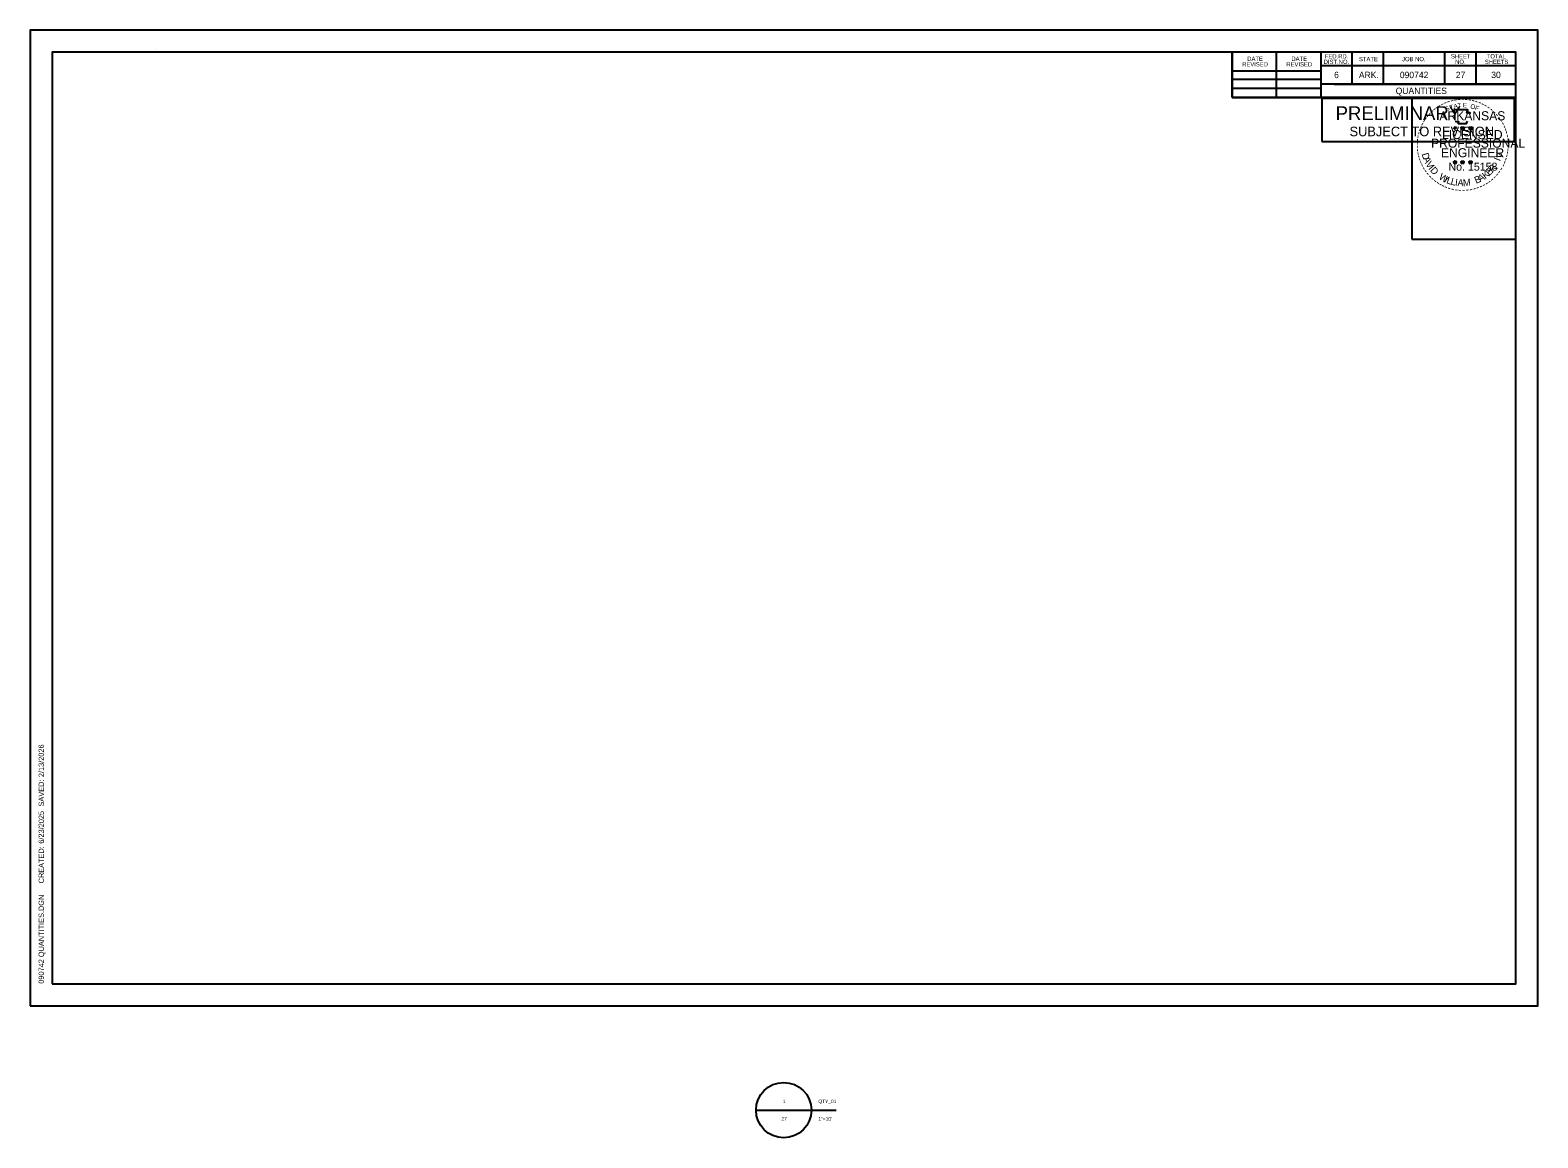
# Model space of a CAD drawing. Extents: x 0 to 373, y -15 to 110.
import ezdxf

# ---------------------------------------------------------------- set-up
doc = ezdxf.new("R2010")
doc.units = 0
for name, color, linetype in [('Default', 7, 'Continuous'), ('SHET_Annotations', 7, 'Continuous'), ('SHET_Border-Lines', 7, 'Continuous'), ('SHET_Border-Text', 7, 'Continuous'), ('SHET_Stamp-Prelim', 7, 'Continuous'), ('SHET_Stamp-Seal', 7, 'Continuous')]:
    doc.layers.add(name, color=color, linetype=linetype)

msp = doc.modelspace()

# ---------------------------------------------------------------- linework, layer by layer
at = {"layer": 'Default'}
for p, q in [((81.85, -11.75), (88.1, -11.75)), ((85, -11.75), (90.87, -11.75))]:
    msp.add_line(p, q, dxfattribs=at)
msp.add_circle((84.97, -11.75), 3.12, dxfattribs=at)
at = {"layer": 'SHET_Border-Lines'}
for p, q in [((14.11, 107.86), (14.11, 107.86)), ((14.11, 107.86), (14.11, 107.86)), ((135.55, 102.41), (135.55, 107.5)), ((140.54, 102.41), (140.54, 107.5)), ((145.52, 107.5), (145.52, 102.41)), ((149.01, 107.5), (149.01, 103.92)), ((152.55, 107.5), (152.55, 103.92)), ((159.47, 107.5), (159.47, 103.92)), ((163.01, 107.5), (163.01, 103.92)), ((135.55, 105.43), (145.52, 105.43)), ((167.5, 105.98), (145.52, 105.98)), ((167.5, 105.99), (167.5, 105.99)), ((135.55, 104.47), (145.52, 104.47)), ((167.5, 103.92), (145.52, 103.92)), ((147.03, 103.92), (167.5, 103.92)), ((135.55, 103.47), (145.52, 103.47)), ((167.5, 102.41), (135.55, 102.41))]:
    msp.add_line(p, q, dxfattribs=at)
for points in [[(0, 0), (170, 0), (170, 110), (0, 110)], [(2.5, 2.5), (167.5, 2.5), (167.5, 107.5), (2.5, 107.5)], [(135.55, 102.41), (167.5, 102.41), (167.5, 107.5), (135.55, 107.5)]]:
    msp.add_lwpolyline(points, close=True, dxfattribs=at)
at = {"layer": 'SHET_Stamp-Prelim'}
for points in [[(145.64, 97.43), (167.38, 97.43), (167.38, 102.29), (145.64, 102.29)], [(156.42, 102.36), (156.6, 102.36), (156.6, 102.4), (156.42, 102.4)]]:
    msp.add_lwpolyline(points, close=True, dxfattribs=at)
at = {"layer": 'SHET_Stamp-Seal'}
for p, q in [((160.48, 99.03), (160.66, 98.97)), ((160.48, 99.03), (160.61, 99)), ((160.48, 99.03), (160.6, 98.96)), ((160.55, 98.82), (160.66, 98.97)), ((160.55, 98.82), (160.61, 98.94)), ((160.55, 98.82), (160.66, 98.93)), ((160.66, 99.15), (160.64, 99.03)), ((160.66, 98.97), (160.66, 99.15)), ((160.66, 99.15), (160.68, 99.03)), ((160.83, 99.03), (160.66, 98.97)), ((160.77, 98.82), (160.66, 98.97)), ((160.77, 98.82), (160.66, 98.93)), ((160.83, 99.03), (160.69, 99)), ((160.77, 98.82), (160.7, 98.97)), ((160.83, 99.03), (160.73, 98.97)), ((161.33, 99.03), (161.51, 98.97)), ((161.33, 99.03), (161.46, 99)), ((161.33, 99.03), (161.45, 98.96)), ((161.4, 98.82), (161.51, 98.97)), ((161.4, 98.82), (161.46, 98.94)), ((161.4, 98.82), (161.51, 98.93)), ((161.51, 99.15), (161.49, 99.03)), ((161.51, 98.97), (161.51, 99.15)), ((161.51, 99.15), (161.53, 99.03)), ((161.69, 99.03), (161.51, 98.97)), ((161.62, 98.82), (161.51, 98.97)), ((161.62, 98.82), (161.51, 98.93)), ((161.69, 99.03), (161.54, 99)), ((161.62, 98.82), (161.55, 98.97)), ((161.69, 99.03), (161.58, 98.97)), ((162.23, 99.02), (162.41, 98.96)), ((162.23, 99.02), (162.36, 99)), ((162.23, 99.02), (162.35, 98.96)), ((162.3, 98.81), (162.41, 98.96)), ((162.3, 98.81), (162.36, 98.94)), ((162.3, 98.81), (162.41, 98.92)), ((162.41, 99.15), (162.39, 99.02)), ((162.41, 98.96), (162.41, 99.15)), ((162.41, 99.15), (162.43, 99.02)), ((162.59, 99.02), (162.41, 98.96)), ((162.52, 98.81), (162.41, 98.96)), ((162.52, 98.81), (162.41, 98.92)), ((162.59, 99.02), (162.44, 98.99)), ((162.52, 98.81), (162.45, 98.96)), ((162.59, 99.02), (162.48, 98.97)), ((160.66, 95.29), (160.63, 95.16)), ((160.66, 95.11), (160.66, 95.29)), ((160.66, 95.29), (160.68, 95.16)), ((161.51, 95.29), (161.49, 95.16)), ((161.51, 95.11), (161.51, 95.29)), ((161.51, 95.29), (161.53, 95.16)), ((162.41, 95.29), (162.39, 95.16)), ((162.41, 95.1), (162.41, 95.29)), ((162.41, 95.29), (162.43, 95.16)), ((160.48, 95.16), (160.66, 95.11)), ((160.48, 95.16), (160.61, 95.14)), ((160.48, 95.16), (160.6, 95.1)), ((160.55, 94.95), (160.66, 95.11)), ((160.55, 94.95), (160.61, 95.08)), ((160.55, 94.95), (160.65, 95.07)), ((160.76, 94.95), (160.65, 95.06)), ((160.83, 95.16), (160.66, 95.11)), ((160.76, 94.95), (160.66, 95.11)), ((160.83, 95.16), (160.69, 95.14)), ((160.76, 94.95), (160.69, 95.1)), ((160.83, 95.16), (160.73, 95.11)), ((161.33, 95.16), (161.51, 95.11)), ((161.33, 95.16), (161.46, 95.14)), ((161.33, 95.16), (161.45, 95.1)), ((161.4, 94.95), (161.51, 95.11)), ((161.4, 94.95), (161.46, 95.08)), ((161.4, 94.95), (161.51, 95.07)), ((161.68, 95.16), (161.51, 95.11)), ((161.62, 94.95), (161.51, 95.11)), ((161.62, 94.95), (161.51, 95.06)), ((161.68, 95.16), (161.54, 95.14)), ((161.62, 94.95), (161.55, 95.1)), ((161.68, 95.16), (161.58, 95.11)), ((162.23, 95.16), (162.41, 95.1)), ((162.23, 95.16), (162.36, 95.13)), ((162.23, 95.16), (162.35, 95.1)), ((162.3, 94.95), (162.41, 95.1)), ((162.3, 94.95), (162.36, 95.07)), ((162.3, 94.95), (162.41, 95.06)), ((162.58, 95.16), (162.41, 95.1)), ((162.52, 94.95), (162.41, 95.1)), ((162.52, 94.95), (162.41, 95.06)), ((162.58, 95.16), (162.44, 95.13)), ((162.52, 94.95), (162.45, 95.1)), ((162.58, 95.16), (162.48, 95.11))]:
    msp.add_line(p, q, dxfattribs=at)
msp.add_lwpolyline([(155.8, 86.43), (167.5, 86.43), (167.5, 102.41), (155.8, 102.41)], close=True, dxfattribs=at)
for points in [[(160.5, 101), (160.64, 100.58)], [(162.29, 100.53), (162.36, 100.68), (162.01, 100.67), (162.09, 101), (160.5, 101)], [(160.75, 99.77), (160.75, 99.72), (161.04, 99.71), (161.01, 99.47), (161.96, 99.47), (162.07, 99.75)], [(161.51, 99.15), (161.62, 98.82), (161.33, 99.03), (161.69, 99.03), (161.4, 98.82), (161.51, 99.15)], [(162.41, 99.15), (162.52, 98.81), (162.23, 99.02), (162.59, 99.02), (162.3, 98.81), (162.41, 99.15)], [(160.66, 95.29), (160.76, 94.95), (160.48, 95.16), (160.83, 95.16), (160.55, 94.95), (160.66, 95.29)], [(161.51, 95.29), (161.62, 94.95), (161.33, 95.16), (161.68, 95.16), (161.4, 94.95), (161.51, 95.29)], [(162.41, 95.29), (162.52, 94.95), (162.23, 95.16), (162.58, 95.16), (162.3, 94.95), (162.41, 95.29)]]:
    msp.add_lwpolyline(points, dxfattribs=at)
for centre, radius in [((160.66, 98.97), 0.0878), ((160.66, 98.97), 0.0737), ((160.66, 98.97), 0.059), ((160.66, 98.97), 0.0505), ((160.66, 98.97), 0.0381), ((160.66, 98.97), 0.0253), ((160.66, 98.97), 0.0151), ((161.51, 98.97), 0.0878), ((161.51, 98.97), 0.0737), ((161.51, 98.97), 0.059), ((161.51, 98.97), 0.0505), ((161.51, 98.97), 0.0381), ((161.51, 98.97), 0.0253), ((161.51, 98.97), 0.0151), ((162.41, 98.96), 0.0878), ((162.41, 98.96), 0.0737), ((162.41, 98.96), 0.059), ((162.41, 98.96), 0.0505), ((162.41, 98.96), 0.0381), ((162.41, 98.96), 0.0253), ((162.41, 98.96), 0.0151), ((160.66, 95.11), 0.0878), ((160.66, 95.11), 0.0737), ((160.66, 95.11), 0.059), ((160.66, 95.11), 0.0505), ((160.66, 95.11), 0.0381), ((160.66, 95.11), 0.0253), ((160.66, 95.11), 0.0151), ((161.51, 95.11), 0.0878), ((161.51, 95.11), 0.0737), ((161.51, 95.11), 0.059), ((161.51, 95.11), 0.0505), ((161.51, 95.11), 0.0381), ((161.51, 95.11), 0.0253), ((161.51, 95.11), 0.0151), ((162.41, 95.1), 0.0878), ((162.41, 95.1), 0.0737), ((162.41, 95.1), 0.059), ((162.41, 95.1), 0.0505), ((162.41, 95.1), 0.0381), ((162.41, 95.1), 0.0253), ((162.41, 95.1), 0.0151)]:
    msp.add_circle(centre, radius, dxfattribs=at)

# ---------------------------------------------------------------- texts
at = {"layer": 'Default'}
for s, p in [('1', (84.87, -10.96)), ('QTY_01', (88.88, -10.96)), ('27', (84.71, -12.93)), ('1"=10\'', (88.88, -12.93))]:
    msp.add_text(s, height=0.394, dxfattribs=at).set_placement(p)
at = {"layer": 'SHET_Annotations'}
for s, p in [('6', (147.03, 104.59)), ('ARK.', (149.82, 104.59)), ('090742', (154.44, 104.59)), ('27', (160.75, 104.59)), ('30', (164.75, 104.6)), ('QUANTITIES', (153.97, 102.8))]:
    msp.add_text(s, height=0.72, dxfattribs=at).set_placement(p)
at = {"layer": 'SHET_Border-Text'}
for s, p in [('FED.RD.', (145.98, 106.81)), ('SHEET', (160.2, 106.81)), ('TOTAL', (164.24, 106.81)), ('REVISED', (136.66, 105.91)), ('DATE', (137.23, 106.54)), ('REVISED', (141.64, 105.91)), ('DATE', (142.21, 106.54)), ('DIST.NO.', (145.85, 106.19)), ('STATE', (149.83, 106.5)), ('JOB NO.', (154.69, 106.5)), ('NO.', (160.68, 106.19)), ('SHEETS', (164.02, 106.19))]:
    msp.add_text(s, height=0.48, dxfattribs=at).set_placement(p)
for s, p in [('2/13/2026', (1.55, 25.79)), ('  SAVED: ', (1.55, 22.02)), ('6/23/2025', (1.55, 18.29)), ('     CREATED: ', (1.55, 12.66)), ('090742 QUANTITIES.DGN', (1.55, 2.5))]:
    msp.add_text(s, height=0.6, rotation=90, dxfattribs=at).set_placement(p)
at = {"layer": 'SHET_Stamp-Prelim'}
for s, height, p in [('PRELIMINARY', 0.013, (156.43, 102.38)), ('SUBJECT TO REVISION', 0.009, (156.45, 102.37)), ('PRELIMINARY', 1.56, (147.2, 99.86)), ('SUBJECT TO REVISION', 1.08, (148.77, 98.04))]:
    msp.add_text(s, height=height, dxfattribs=at).set_placement(p)
at = {"layer": 'SHET_Stamp-Seal'}
for s, height, rotation, p in [('-', 0.816, 19.1761, (159.86, 101.58)), ('-', 0.816, 13.6302, (160.24, 101.7)), ('-', 0.816, 10.2193, (160.59, 101.78)), ('-', 0.816, 5.8968, (160.96, 101.84)), ('-', 0.816, 0.1862, (161.36, 101.88)), ('-', 0.816, 357.743, (161.72, 101.87)), ('-', 0.816, 352.1617, (162.1, 101.84)), ('-', 0.816, 347.2049, (162.47, 101.78)), ('-', 0.816, 342.3362, (162.79, 101.7)), ('-', 0.816, 50.6142, (157.72, 99.99)), ('-', 0.816, 48.4231, (157.92, 100.24)), ('-', 0.816, 42.9622, (158.15, 100.48)), ('-', 0.816, 38.9507, (158.37, 100.7)), ('-', 0.816, 36.2317, (158.62, 100.89)), ('-', 0.816, 34.0636, (158.91, 101.09)), ('-', 0.816, 28.7918, (159.22, 101.28)), ('-', 0.816, 24.3072, (159.54, 101.44)), ('S', 0.51, 21.594, (159.66, 100.84)), ('T', 0.51, 16.4036, (160.13, 101.01)), ('A', 0.51, 11.2132, (160.55, 101.14)), ('T', 0.51, 6.0228, (160.98, 101.22)), ('E', 0.51, 0.8323, (161.55, 101.28)), ('O', 0.51, 350.4515, (162.36, 101.17)), ('F', 0.51, 340.0707, (162.85, 101.05)), ('-', 0.816, 337.8551, (163.17, 101.59)), ('-', 0.816, 334.1211, (163.49, 101.45)), ('-', 0.816, 329.6409, (163.79, 101.31)), ('-', 0.816, 325.8627, (164.11, 101.12)), ('-', 0.816, 320.5297, (164.43, 100.91)), ('-', 0.816, 315.5786, (164.73, 100.66)), ('-', 0.816, 309.8797, (165.02, 100.38)), ('-', 0.816, 72.3945, (156.94, 98.49)), ('-', 0.816, 67.7743, (157.05, 98.81)), ('-', 0.816, 62.8713, (157.18, 99.12)), ('-', 0.816, 58.0706, (157.34, 99.43)), ('-', 0.816, 54.2325, (157.51, 99.7)), ('-', 0.816, 306.6522, (165.29, 100.07)), ('-', 0.714, 303.6753, (165.54, 99.78)), ('-', 0.816, 299.6684, (165.7, 99.47)), ('-', 0.816, 294.6628, (165.86, 99.16)), ('-', 0.816, 290.5728, (166, 98.86)), ('-', 0.816, 285.1233, (166.11, 98.57)), ('-', 0.816, 94.1959, (156.74, 96.68)), ('-', 0.816, 89.0622, (156.72, 97.05)), ('-', 0.816, 85.1863, (156.73, 97.41)), ('-', 0.816, 81.2013, (156.77, 97.76)), ('-', 0.816, 75.461, (156.84, 98.12)), ('-', 0.816, 280.5493, (166.22, 98.19)), ('-', 0.816, 276.5962, (166.3, 97.8)), ('-', 0.816, 274.3301, (166.33, 97.43)), ('-', 0.816, 269.9407, (166.35, 97.11)), ('-', 0.816, 98.9479, (156.77, 96.34)), ('-', 0.816, 101.7149, (156.84, 95.97)), ('-', 0.816, 105.4578, (156.93, 95.66)), ('-', 0.816, 109.0874, (157.04, 95.34)), ('-', 0.816, 114.0643, (157.17, 95.04)), ('D', 0.785, 286.2848, (156.89, 96.04)), ('A', 0.785, 292.7835, (157.04, 95.53)), ('V', 0.785, 300.7936, (157.3, 94.92)), ('I', 0.785, 69.0301, (165.75, 95.17)), ('V', 0.785, 72.6573, (165.86, 95.44)), ('-', 0.816, 247.8887, (166.04, 95.38)), ('-', 0.816, 252.8681, (166.15, 95.72)), ('-', 0.816, 255.7626, (166.25, 96.09)), ('-', 0.816, 260.9953, (166.3, 96.43)), ('-', 0.816, 263.5172, (166.34, 96.77)), ('-', 0.816, 115.7289, (157.32, 94.72)), ('-', 0.816, 120.4471, (157.5, 94.42)), ('-', 0.816, 125.8934, (157.71, 94.14)), ('-', 0.816, 130.7181, (157.94, 93.86)), ('I', 0.785, 308.3502, (157.62, 94.4)), ('-', 0.816, 134.2238, (158.21, 93.58)), ('D', 0.785, 311.9774, (157.8, 94.16)), ('W', 0.785, 328.0731, (158.76, 93.26)), ('I', 0.785, 336.6877, (159.36, 92.9)), ('B', 0.785, 22.8589, (163.04, 92.67)), ('A', 0.785, 28.9042, (163.5, 92.86)), ('K', 0.785, 36.9143, (164.07, 93.19)), ('E', 0.785, 44.0175, (164.53, 93.54)), ('R', 0.785, 50.3651, (164.91, 93.9)), ('-', 0.816, 225.7653, (165.04, 93.76)), (',', 0.785, 57.4684, (165.27, 94.35)), ('-', 0.816, 231.2538, (165.28, 94.05)), ('-', 0.816, 233.8452, (165.5, 94.34)), ('-', 0.816, 239.0712, (165.7, 94.67)), ('-', 0.816, 244.6197, (165.91, 95.06)), ('-', 0.816, 138.9338, (158.48, 93.34)), ('-', 0.816, 144.6463, (158.76, 93.13)), ('-', 0.816, 148.0898, (159.05, 92.94)), ('-', 0.816, 151.5704, (159.34, 92.78)), ('-', 0.816, 154.6002, (159.61, 92.65)), ('-', 0.816, 158.5612, (159.92, 92.52)), ('L', 0.785, 340.3149, (159.63, 92.77)), ('-', 0.816, 162.7983, (160.28, 92.41)), ('L', 0.785, 346.6625, (160.12, 92.6)), ('-', 0.816, 167.5555, (160.64, 92.33)), ('-', 0.816, 173.1155, (161.03, 92.27)), ('I', 0.785, 353.0101, (160.63, 92.47)), ('A', 0.785, 356.6373, (160.92, 92.43)), ('-', 0.816, 176.5183, (161.41, 92.25)), ('-', 0.816, 181.5918, (161.79, 92.26)), ('M', 0.785, 4.6473, (161.58, 92.4)), ('-', 0.816, 185.8167, (162.21, 92.3)), ('-', 0.816, 191.2858, (162.58, 92.36)), ('-', 0.816, 195.4743, (162.95, 92.47)), ('-', 0.816, 199.4643, (163.29, 92.59)), ('-', 0.816, 204.2516, (163.62, 92.73)), ('-', 0.816, 207.3568, (163.93, 92.89)), ('-', 0.816, 212.2491, (164.22, 93.07)), ('-', 0.816, 215.7363, (164.49, 93.26)), ('-', 0.816, 221.0851, (164.77, 93.5))]:
    msp.add_text(s, height=height, rotation=rotation, dxfattribs=at).set_placement(p)
for s, height, p in [('ARKANSAS', 1.02, (158.9, 99.84)), ('LICENSED', 1.02, (159.2, 97.72)), ('PROFESSIONAL', 1.02, (157.96, 96.75)), ('ENGINEER', 1.02, (159.08, 95.67)), ('No. 15158', 0.896, (159.92, 94.16)), ('AAMU', 0.0000102, (161.47, 92.4))]:
    msp.add_text(s, height=height, dxfattribs=at).set_placement(p)

doc.saveas('drawing.dxf')
